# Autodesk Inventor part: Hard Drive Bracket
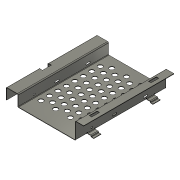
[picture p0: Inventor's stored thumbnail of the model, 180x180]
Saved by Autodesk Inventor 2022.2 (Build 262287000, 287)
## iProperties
Created: 2007-02
Part Number: Hard Drive Bracket
Material: アルミニウム 6061
Document SubType Name: Sheet Metal
Designer: Autodesk, Inc.
Mass: 80.2966 g
Surface Area: 618.59 cm^2
Volume: 29.7395 cm^3
Density: 2.7 g/cm^3
Flat Pattern Width: 16 cm
Flat Pattern Length: 21.2648 cm
Flat Pattern Area: 340.236 cm^2
Sheet Metal Rule: Default_mm
Sheet Metal Width: 160.000 mm
Sheet Metal Length: 212.648 mm
Sheet Metal Area: 34023.646 mm^2
Appearance: Silicon Nitride - Polished
Length: =<FLAT PATTERN LENGTH> cm
Width: =<FLAT PATTERN WIDTH> cm
Author: Autodesk, Inc.
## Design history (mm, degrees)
node "Face1"
  sketch "Sketch1"
    geometry: L1 (-50.5, 80)-(50.5, 80); L2 (50.5, 80)-(50.5, -80); L3 (50.5, -80)-(-50.5, -80); L4 (-50.5, -80)-(-50.5, 80); L5 (-50.5, -80)-(50.5, 80); 2 further points
    constraints: 10 end point, 2 parallel, 1 coincident, 1 horizontal, 1 midpoint, 1 perpendicular
    dimensions: "d0" = 101 distance of L1.start L1.end; "d1" = 160 distance of L3.end L1.start
node "Contour Flange1"
  sketch "Sketch2"
    geometry: L1 (101, 0)-(101, 29.2); L2 (101, 29.2)-(116, 29.2)
    constraints: 4 end point, 1 perpendicular, 1 vertical
    dimensions: "d3" = 29.2 distance of L1.start L1.end (computed from Thickness); "d4" = 15 distance of L1.end L2.end
sketch "Sketch3"
  geometry: L1 (49.7, 80)-(51.51, 80) reference; L2 (49.7, -80)-(-50.5, -80) reference; L3 (-50.5, -80)-(-50.5, 80) reference; L4 (-50.5, 80)-(49.7, 80) reference; L5 (49.7, -80)-(51.51, -80) reference; L6 (51.51, -80)-(78.31, -80) reference; L7 (78.31, 80)-(51.51, 80) reference; L8 (78.31, -80)-(80.119, -80) reference; L9 (93.519, 80)-(80.119, 80) reference; L10 (80.119, 80)-(78.31, 80) reference; L11 (80.119, -80)-(93.519, -80) reference; L12 (93.519, 80)-(93.519, -80) reference; L13 (78.31, 80)-(78.31, -80) reference; L14 (80.119, 80)-(80.119, -80) reference; L15 (79.214, 80)-(79.214, -80) reference; L16 (49.7, -80)-(49.7, 80) reference; L17 (51.51, -80)-(51.51, 80) reference; L18 (50.605, -80)-(50.605, 80) reference; L19 (34.7, 60)-(58.31, 60); L20 (58.31, 60)-(58.31, 45); L21 (58.31, 45)-(34.7, 45); L22 (34.7, 45)-(34.7, 60)
  constraints: 8 end point, 2 parallel, 1 horizontal, 1 perpendicular
  dimensions: "d29" = 20 distance between parallel lines of L13 L20; "d30" = 15 distance between parallel lines of L16 L22; "d31" = 20 distance between parallel lines of L4 L19; "d32" = 15 distance of L21.end L19.start
cut "Cut1" sketch "Sketch3" dims "d18" = 0.8 (= Thickness), "d19" = 0
node "Face3"
  sketch "Sketch5"
    geometry: L1 (0, 0)-(5.5, 0); L2 (6, -0.5)-(6, -0.5); L3 (7.5, -2)-(11, -2); A1 r 0.5 centre (5.5, -0.5) between (6, -0.5) and (5.5, 0); A2 r 1.5 centre (7.5, -0.5) between (6, -0.5) and (7.5, -2); 2 further points
    constraints: 6 end point, 4 point on circle, 4 point on line, 4 tangent, 2 centre point, 1 horizontal, 1 parallel, 1 perpendicular
    dimensions: "d67" = 2 distance of point (6, 0) point (6, -2); "d68" = 5 distance of point (6, -2) L3.end; "d69" = 0.5 radius of A1; "d70" = 1.5 radius of A2; "d71" = 5.5 distance of L1.start L1.end
node "Contour Flange2"
sketch "Sketch6"
  geometry: L1 (-3.2, 139)-(-3.2, 126) reference; L2 (-6.7, 126)-(-3.2, 126) reference; L3 (-6.7, 139)-(-3.2, 139) reference; L4 (-8.7, 139)-(-8.7, 126) reference; L5 (-10.7, 139.5)-(-6.2, 139.5); L6 (-6.2, 139.5)-(-6.2, 125.5); L7 (-6.2, 125.5)-(-10.7, 125.5); L8 (-10.7, 125.5)-(-10.7, 139.5)
  constraints: 8 end point, 2 parallel, 1 horizontal, 1 perpendicular
  dimensions: "d72" = 3 distance between parallel lines of L1 L6; "d73" = 0.5 distance between parallel lines of L2 L7; "d74" = 0.5 distance between parallel lines of L5 L3; "d75" = 2 distance between parallel lines of L8 L4
cut "Cut2" sketch "Sketch6" dims "d76" = 0.8 (= Thickness), "d77" = 0
mirror "Mirror1"
node "Contour Flange3"
  sketch "Sketch7"
    geometry: L1 (0, 0)-(0, 19.8); L2 (0, 19.8)-(-21.6, 19.8); L3 (-21.6, 19.8)-(-21.6, 0)
    constraints: 6 end point, 1 parallel, 1 perpendicular, 1 vertical
    dimensions: "d86" = 19.8 distance of L1.start L1.end (computed from Thickness); "d87" = 21.6 distance of L1.end L2.end (computed from Thickness); "d88" = 19.8 distance of L2.end L3.end (= d86)
sketch "Sketch9"
  geometry: L1 (28.2, 88)-(28.2, 100) reference; L2 (0, 0)-(18.2, 0) reference; L3 (18.2, 0)-(18.2, 88) reference; L4 (28.2, 100)-(18.2, 100) reference; L5 (18.2, 160)-(0, 160) reference; L6 (-1.81, 0)-(0, 0) reference; L7 (0, 160)-(-1.81, 160) reference; L8 (18.2, 88)-(28.2, 88) reference; L9 (18.2, 100)-(18.2, 160) reference; L10 (-1.81, 160)-(-20.21, 160) reference; L11 (-20.21, 0)-(-20.21, 160) reference; L12 (-20.21, 0)-(-1.81, 0) reference; L13 (0, 0)-(0, 160) reference; L14 (-1.81, 0)-(-1.81, 160) reference; L15 (-0.905, 0)-(-0.905, 160) reference; L16 (5, 86)-(-6.81, 86); L17 (-6.81, 86)-(-6.81, 102); L18 (-6.81, 102)-(5, 102); L19 (5, 102)-(5, 86)
  constraints: 8 end point, 2 parallel, 1 horizontal, 1 perpendicular
  dimensions: "d97" = 2 distance between parallel lines of L18 L4; "d98" = 2 distance between parallel lines of L16 L8 (= d97); "d99" = 5 distance between parallel lines of L14 L17; "d100" = 5 distance between parallel lines of L13 L19
cut "Cut3" sketch "Sketch9" dims "d101" = 0.8 (= Thickness), "d102" = 0
sketch "Sketch10"
  geometry: L1 (18.2, 88)-(28.2, 88) reference; L2 (28.2, 88)-(28.2, 100) reference; 1 further point
  dimensions: "d103" = 6 distance from line of point (23.2, 94) L1; "d104" = 5 distance from line of point (23.2, 94) L2
feature "iFeature1:1" sketch "Sketch10"
sketch "Sketch11"
  geometry: L1 (26.8, 35)-(28.61, 35) reference; L2 (26.216, 21)-(26.8, 21) reference; L3 (28.61, 20)-(28.61, 0) reference; L4 (128.01, 160)-(28.61, 160) reference; L5 (26.8, 126)-(26.216, 126) reference; L6 (26.8, 21)-(26.8, 34) reference; L7 (26.8, 20)-(26.216, 20) reference; L8 (128.01, 0)-(128.01, 160) reference; L9 (26.8, 160)-(0, 160) reference; L10 (26.8, 126)-(26.8, 139) reference; L11 (28.61, 125)-(26.8, 125) reference; L12 (28.61, 125)-(28.61, 35) reference; L13 (28.61, 160)-(28.61, 140) reference; L14 (28.61, 140)-(43.61, 140) reference; L15 (43.61, 140)-(43.61, 125) reference; L16 (28.61, 35)-(43.61, 35) reference; L17 (26.8, 125)-(26.216, 125) reference; L18 (26.216, 140)-(26.8, 140) reference; L19 (26.8, 125)-(26.8, 35) reference; L20 (43.61, 125)-(28.61, 125) reference; L21 (26.8, 160)-(26.8, 140) reference; L22 (28.61, 0)-(128.01, 0) reference; L23 (43.61, 35)-(43.61, 20) reference; L24 (43.61, 20)-(28.61, 20) reference; L25 (26.8, 20)-(26.8, 0) reference; L26 (26.216, 35)-(26.8, 35) reference; L27 (26.216, 139)-(26.8, 139) reference; L28 (26.8, 34)-(26.216, 34) reference; L29 (0, 160)-(0, 0) reference; L30 (0, 0)-(26.8, 0) reference; L31 (27.738, 35)-(27.738, 125) reference; A1 r 0.5 centre (26.216, 139.5) between (26.216, 140) and (26.216, 139) reference; A2 r 0.5 centre (26.216, 20.5) between (26.216, 21) and (26.216, 20) reference; A3 r 0.5 centre (26.216, 34.5) between (26.216, 35) and (26.216, 34) reference; A4 r 0.5 centre (26.216, 125.5) between (26.216, 126) and (26.216, 125) reference; 1 further point
  dimensions: "d106" = 6 distance from line of L12 point (22.61, 131.5); "d107" = 28.5 distance from line of L9 point (22.61, 131.5)
feature "iFeature2:1" sketch "Sketch11"
sketch "Sketch12" dims "d116" = 10
  geometry: L1 (26.8, 125)-(26.216, 125) reference; L2 (26.8, 21)-(26.8, 34) reference; L3 (26.8, 34)-(26.216, 34) reference; L4 (26.216, 35)-(26.8, 35) reference; L5 (43.61, 20)-(28.61, 20) reference; L6 (43.61, 35)-(43.61, 20) reference; L7 (28.61, 35)-(43.61, 35) reference; L8 (43.61, 125)-(28.61, 125) reference; L9 (28.61, 0)-(128.01, 0) reference; L10 (128.01, 160)-(28.61, 160) reference; L11 (28.61, 160)-(28.61, 140) reference; L12 (28.61, 140)-(43.61, 140) reference; L13 (43.61, 140)-(43.61, 125) reference; L14 (26.8, 125)-(26.8, 35) reference; L15 (28.61, 125)-(28.61, 35) reference; L16 (0, 160)-(0, 0) reference; L17 (26.8, 20)-(26.8, 0) reference; L18 (26.8, 20)-(26.216, 20) reference; L19 (28.61, 20)-(28.61, 0) reference; L20 (26.216, 21)-(26.8, 21) reference; L21 (128.01, 0)-(128.01, 160) reference; L22 (28.61, 125)-(26.8, 125) reference; L23 (0, 0)-(26.8, 0) reference; L24 (26.8, 160)-(0, 160) reference; L25 (26.8, 160)-(26.8, 140) reference; L26 (26.216, 140)-(26.8, 140) reference; L27 (26.216, 139)-(26.8, 139) reference; L28 (26.8, 126)-(26.8, 139) reference; L29 (26.8, 126)-(26.216, 126) reference; L30 (26.8, 35)-(28.61, 35) reference; L31 (27.738, 35)-(27.738, 125) reference; A1 r 0.5 centre (26.216, 34.5) between (26.216, 35) and (26.216, 34) reference; A2 r 0.5 centre (26.216, 20.5) between (26.216, 21) and (26.216, 20) reference; A3 r 0.5 centre (26.216, 125.5) between (26.216, 126) and (26.216, 125) reference; A4 r 0.5 centre (26.216, 139.5) between (26.216, 140) and (26.216, 139) reference; A5 r 1.5 centre (22.61, 131.5) between (24.11, 131.5) and (24.11, 131.5) reference; 2 further points
  constraints: 1 vertical, 1 other
  dimensions: "d109" = 40.5 distance of point (22.61, 91) A5.centre; "d110" = 6 distance from line of point (22.61, 91) L15; "d113" = 55 distance of point (22.61, 91) point (22.61, 36)
feature "iFeature3:1" sketch "Sketch12" dims "d118" = 3 (= d119), "d119" = 3, "d120" = 8
mirror "Mirror2"
feature "iFeature4:1"
body "Solid1"
node "Face2"
face "Plate1" dims "d138" = 0.8 (= Thickness)
face "Plate2" dims "d5" = 0.8 (= BendReliefWidth), "d6" = 0.4 (= BendReliefDepth), "d7" = 1.6 (= MinimumRemnant), "d8" = 0.8 (= BendRadius), "d9" = 0.8 (= BendRadius), "d10" = 1, "d11" = 3.2 (= CornerReliefSize), "d12" = 0.8 (= Thickness), "d135" = 0.8 (= JacobiRadiusSize), "d138" = 0.8 (= Thickness), "SeamGap" = 0.01
bend "Bend1" dims "d5" = 0.8 (= BendReliefWidth), "d6" = 0.4 (= BendReliefDepth), "d7" = 1.6 (= MinimumRemnant), "d8" = 0.8 (= BendRadius), "d9" = 0.8 (= BendRadius), "d10" = 1, "d138" = 0.8 (= Thickness), "SeamGap" = 0.01
feature "Corner1" dims "d10" = 1, "d11" = 3.2 (= CornerReliefSize), "d12" = 0.8 (= Thickness), "d135" = 0.8 (= JacobiRadiusSize)
sketch "Sketch4"
  geometry: L1 (-20, 140)-(-26.216, 140); L2 (-26.216, 139)-(-28.4, 139); L3 (-28.4, 139)-(-28.4, 126); L4 (-28.4, 126)-(-26.216, 126); L5 (-26.216, 125)-(-20, 125); L6 (-20, 125)-(-20, 140); L7 (-28.4, 125)-(-28.4, 140) reference; A1 r 0.5 centre (-26.216, 139.5) between (-26.216, 139) and (-26.216, 140); A2 r 0.5 centre (-26.216, 125.5) between (-26.216, 125) and (-26.216, 126)
  constraints: 12 end point, 4 point on circle, 4 tangent, 3 parallel, 2 centre point, 1 collinear, 1 horizontal
  dimensions: "d33" = 0.5 radius of A2; "d34" = 0.5 radius of A1 (= d33)
face "Plate4" dims "d35" = 0.8 (= BendRadius), "d38" = 1.6 (= MinimumRemnant), "d138" = 0.8 (= Thickness), "SeamGap" = 0.01
bend "Bend2" dims "d35" = 0.8 (= BendRadius), "d36" = 0.8 (= BendReliefWidth), "d37" = 0.4 (= BendReliefDepth), "d38" = 1.6 (= MinimumRemnant), "d39" = 0.8 (= BendRadius), "d138" = 0.8 (= Thickness), "SeamGap" = 0.01
face "Plate7" dims "d58" = 0.8 (= BendReliefWidth), "d59" = 0.4 (= BendReliefDepth), "d60" = 1.6 (= MinimumRemnant), "d61" = 0.8 (= BendRadius), "d62" = 0.8 (= BendRadius), "d63" = 1, "d64" = 3.2 (= CornerReliefSize), "d65" = 0.8 (= Thickness), "d136" = 0.8 (= JacobiRadiusSize), "d138" = 0.8 (= Thickness), "SeamGap" = 0.01
bend "Bend3" dims "d58" = 0.8 (= BendReliefWidth), "d59" = 0.4 (= BendReliefDepth), "d60" = 1.6 (= MinimumRemnant), "d61" = 0.8 (= BendRadius), "d62" = 0.8 (= BendRadius), "d63" = 1, "d138" = 0.8 (= Thickness), "SeamGap" = 0.01
feature "Corner4" dims "d63" = 1, "d64" = 3.2 (= CornerReliefSize), "d65" = 0.8 (= Thickness), "d136" = 0.8 (= JacobiRadiusSize)
face "Plate8" dims "d78" = 0.8 (= BendReliefWidth), "d79" = 0.4 (= BendReliefDepth), "d80" = 1.6 (= MinimumRemnant), "d81" = 0.8 (= BendRadius), "d82" = 0.8 (= BendRadius), "d83" = 1, "d84" = 3.2 (= CornerReliefSize), "d85" = 0.8 (= Thickness), "d137" = 0.8 (= JacobiRadiusSize), "d138" = 0.8 (= Thickness), "SeamGap" = 0.01
bend "Bend4" dims "d78" = 0.8 (= BendReliefWidth), "d79" = 0.4 (= BendReliefDepth), "d80" = 1.6 (= MinimumRemnant), "d81" = 0.8 (= BendRadius), "d82" = 0.8 (= BendRadius), "d83" = 1, "d138" = 0.8 (= Thickness), "SeamGap" = 0.01
feature "Corner5" dims "d83" = 1, "d84" = 3.2 (= CornerReliefSize), "d85" = 0.8 (= Thickness), "d137" = 0.8 (= JacobiRadiusSize)
sketch "Sketch8"
  geometry: L1 (0, 88)-(10, 88); L2 (10, 88)-(10, 100); L3 (10, 100)-(0, 100); L4 (0, 100)-(0, 88); L5 (0, 160)-(-18.2, 160) reference; L6 (0, 0)-(0, 160) reference
  constraints: 8 end point, 2 parallel, 1 collinear, 1 horizontal, 1 perpendicular
  dimensions: "d89" = 12 distance of L1.end L2.end; "d90" = 10 distance of L1.start L1.end; "d91" = 60 distance between parallel lines of L5 L3
face "Plate9" dims "d92" = 0.8 (= BendRadius), "d95" = 1.6 (= MinimumRemnant), "d138" = 0.8 (= Thickness), "SeamGap" = 0.01
bend "Bend5" dims "d92" = 0.8 (= BendRadius), "d93" = 0.8 (= BendReliefWidth), "d94" = 0.4 (= BendReliefDepth), "d95" = 1.6 (= MinimumRemnant), "d96" = 0.8 (= BendRadius), "d138" = 0.8 (= Thickness), "SeamGap" = 0.01
sketch "Sketch13"
  geometry: L1 (109.129, 20)-(109.129, 80) reference; L2 (109.129, 80)-(90.929, 80) reference; L3 (70.719, -80)-(89.119, -80) reference; L4 (89.119, -80)-(89.119, 6) reference; L5 (89.119, 22)-(90.929, 22) reference; L6 (90.929, 80)-(89.119, 80) reference; L7 (90.929, 22)-(95.929, 22) reference; L8 (95.929, 22)-(95.929, 6) reference; L9 (95.929, 6)-(90.929, 6) reference; L10 (89.119, 80)-(70.719, 80) reference; L11 (90.929, -80)-(90.929, 6) reference; L12 (90.929, -80)-(109.129, -80) reference; L13 (57.2, 13.5)-(57.2, 8.5) reference; L14 (70.719, 80)-(68.91, 80) reference; L15 (68.91, -80)-(70.719, -80) reference; L16 (89.119, 6)-(84.119, 6) reference; L17 (84.119, 6)-(84.119, 22) reference; L18 (84.119, 22)-(89.119, 22) reference; L19 (119.129, 8)-(119.129, 20) reference; L20 (-34.7, -45)-(-34.7, -60) reference; L21 (-49.7, 45)-(-49.7, -45) reference; L22 (-34.7, 45)-(-49.7, 45) reference; L23 (51.51, -80)-(68.91, -80) reference; L24 (-49.7, 60)-(-34.7, 60) reference; L25 (-49.7, -45)-(-34.7, -45) reference; L26 (-34.7, -60)-(-49.7, -60) reference; L27 (-49.7, -80)-(49.7, -80) reference; L28 (49.7, -80)-(51.51, -80) reference; L29 (68.91, 80)-(51.51, 80) reference; L30 (-49.7, 80)-(-49.7, 60) reference; L31 (54.2, -46.5)-(54.2, -41.5) reference; L32 (-34.7, 60)-(-34.7, 45) reference; L33 (49.7, 80)-(-49.7, 80) reference; L34 (49.7, 80)-(51.51, 80) reference; L35 (119.129, 20)-(109.129, 20) reference; L36 (109.129, -80)-(109.129, 8) reference; L37 (109.129, 8)-(119.129, 8) reference; L38 (-49.7, -60)-(-49.7, -80) reference; L39 (57.2, -41.5)-(57.2, -46.5) reference; L40 (54.2, 8.5)-(54.2, 13.5) reference; L41 (49.7, -80)-(49.7, 80) reference; L42 (51.51, -80)-(51.51, 80) reference; L43 (68.91, -80)-(68.91, 80) reference; L44 (70.719, -80)-(70.719, 80) reference; L45 (89.119, 22)-(89.119, 80) reference; L46 (90.929, 22)-(90.929, 80) reference; L47 (69.814, -80)-(69.814, 80) reference; L48 (90.691, 22)-(90.691, 80) reference; L49 (50.605, 80)-(50.605, -80) reference; L50 (27.105, 42.5)-(40.096, 50); L51 (40.096, 50)-(40.096, 35); L52 (40.096, 35)-(27.105, 42.5); A1 r 2 centre (114.129, 14) between (116.129, 14) and (116.129, 14) reference; A2 r 1.5 centre (55.7, 51.5) between (54.2, 51.5) and (54.2, 51.5) reference; A3 r 1.5 centre (55.7, -46.5) between (54.2, -46.5) and (57.2, -46.5) reference; A4 r 1.5 centre (55.7, -41.5) between (57.2, -41.5) and (54.2, -41.5) reference; A5 r 1.5 centre (55.7, 8.5) between (54.2, 8.5) and (57.2, 8.5) reference; A6 r 1.5 centre (55.7, 13.5) between (57.2, 13.5) and (54.2, 13.5) reference; 49 further points
  constraints: 6 end point, 2 coincident, 1 horizontal, 1 vertical, 53 other
  dimensions: "d122" = 69.03307 distance from line of point (40.096, 50) L1; "d123" = 15 distance of L50.end L51.end; "d124" = 30 distance from line of L33 point (40.096, 50); "d125" = 12.99038 distance from line of point (27.105, 42.5) L51 (derived); "d128" = 15 distance of point (27.105, 42.5) point (27.105, 27.5); "d131" = 25.98076 distance of point (27.105, 42.5) point (1.124, 42.5) (= 2 x d125)
feature "Definition1" dims "d0" = 0.8 (derived)
other parameters: "Thickness" = 0.8 (derived), "BendRadius" = 0.8 (= Thickness), "BendReliefWidth" = 0.8 (= Thickness), "BendReliefDepth" = 0.4 (= 0.5 x Thickness), "CornerReliefSize" = 3.2 (= 4 x Thickness), "MinimumRemnant" = 1.6 (= 2 x Thickness), "TransitionRadius" = 0.8 (= BendRadius), "JacobiRadiusSize" = 0.8 (= BendRadius), "d2" = 0.8 (= BendRadius), "d105" = 0, "d108" = 0, "d121" = 90 deg, "d134" = 0, "GapSize" = 0.8 (= Thickness), "BendRadius" = 0.8, "BendReliefDepth" = 0.4, "BendReliefWidth" = 0.8, "CornerReliefSize" = 3.2, "JacobiRadiusSize" = 0.8, "MinimumRemnant" = 1.6, "Thickness" = 0.8, "TransitionRadius" = 0.8, "GapSize" = 0.8, "d1" = 0
